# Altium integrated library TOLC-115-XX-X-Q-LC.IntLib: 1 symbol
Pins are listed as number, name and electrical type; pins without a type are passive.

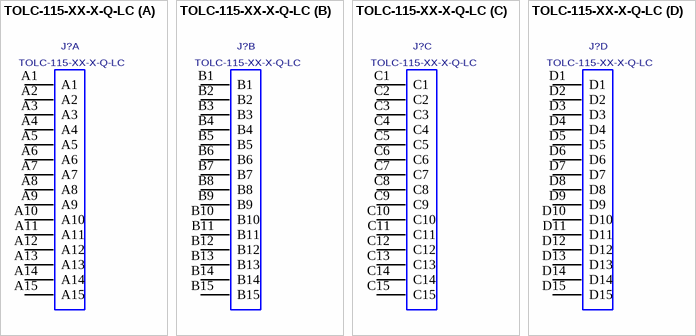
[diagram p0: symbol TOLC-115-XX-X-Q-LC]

## TOLC-115-XX-X-Q-LC
designator J?
QUAD ROW STAGGERED SMT TERMINAL ASSEMBLY, .050" (1.27mm) PITCH, 60PINS, LOCKING CLIPS.; MANUFACTURER: SAMTEC
footprint TOLC-115-XX-X-Q-LC
part A pins: A1, A2, A3, A4, A5, A6, A7, A8, A9, A10, A11, A12, A13, A14, A15
part B pins: B1, B2, B3, B4, B5, B6, B7, B8, B9, B10, B11, B12, B13, B14, B15
part C pins: C1, C2, C3, C4, C5, C6, C7, C8, C9, C10, C11, C12, C13, C14, C15
part D pins: D1, D2, D3, D4, D5, D6, D7, D8, D9, D10, D11, D12, D13, D14, D15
